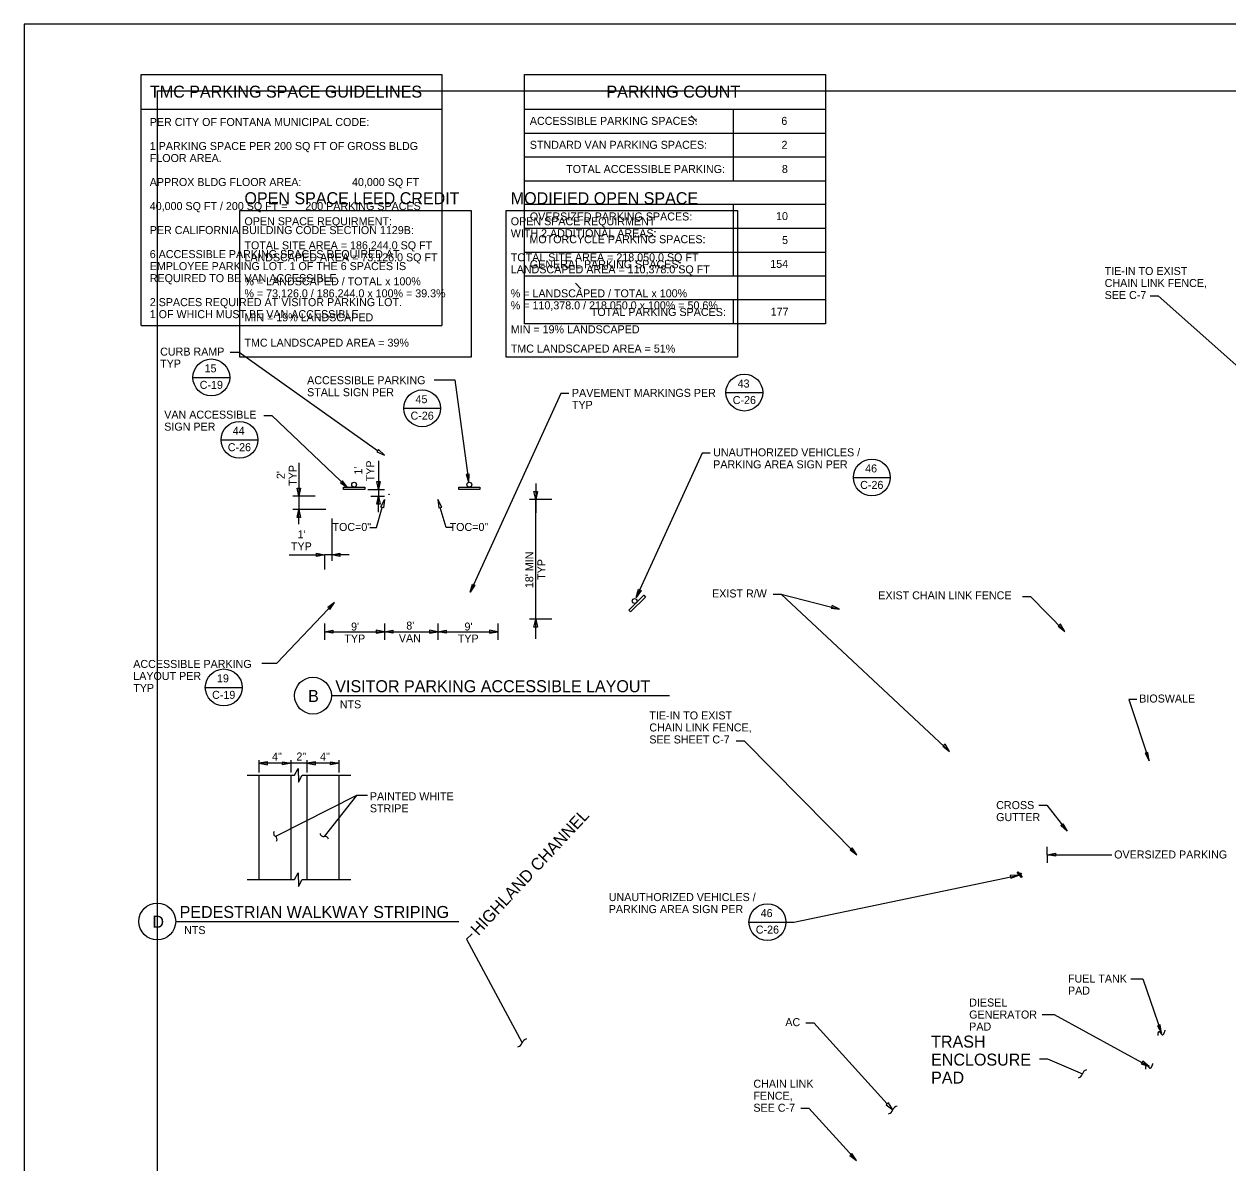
# Model space of a CAD drawing. Extents: x 0 to 4.19, y 0 to 2.5.
# Drawn here: x 0 to 1.504, y 1.078 to 2.5 of the extents above; entities that cross this region are included whole.
import ezdxf

# ---------------------------------------------------------------- set-up
doc = ezdxf.new("R2010")
doc.units = 0
for name, color, linetype in [('C-MARK', 7, 'Continuous'), ('C-PRKG-STRP', 7, 'Continuous'), ('C-RAMP-Bumps', 7, 'Continuous'), ('C-TEXT', 7, 'Continuous'), ('C-TEXT-SUBT', 7, 'Continuous'), ('C-TEXT-TITL', 7, 'Continuous'), ('G-TTLB-OTLN', 7, 'Continuous'), ('G-TTLB-VIEW', 7, 'Continuous'), ('LEED TABLE', 7, 'Continuous'), ('Level 11', 7, 'Continuous'), ('PARING COUNT', 7, 'Continuous')]:
    doc.layers.add(name, color=color, linetype=linetype)

msp = doc.modelspace()

# ---------------------------------------------------------------- linework, layer by layer
at = {"layer": 'C-MARK'}
for p, q in [((0.2109, 2.0587), (0.2569, 2.0587)), ((0.8768, 2.0397), (0.9228, 2.0397)), ((0.4744, 2.0201), (0.5204, 2.0201)), ((0.2461, 1.9808), (0.2921, 1.9808)), ((0.3433, 1.9521), (0.3433, 1.9102)), ((0.4429, 1.9543), (0.4429, 1.9186)), ((0.6391, 1.9261), (0.6391, 1.9061)), ((1.0361, 1.9337), (1.0821, 1.9337)), ((0.3636, 1.9102), (0.3358, 1.9102)), ((0.3433, 1.9102), (0.3433, 1.8936)), ((0.4293, 1.9186), (0.4504, 1.9186)), ((0.433, 1.9102), (0.4504, 1.9102)), ((0.4429, 1.9186), (0.4429, 1.9102)), ((0.4429, 1.8902), (0.4429, 1.9102)), ((0.6595, 1.9061), (0.6316, 1.9061)), ((0.6391, 1.9061), (0.6391, 1.8894)), ((0.6391, 1.7322), (0.6391, 1.9061)), ((0.377, 1.8936), (0.3358, 1.8936)), ((0.3433, 1.8754), (0.3433, 1.8936)), ((0.3845, 1.8823), (0.3845, 1.8297)), ((0.3313, 1.8372), (0.3753, 1.8372)), ((0.3845, 1.8372), (0.3753, 1.8372)), ((0.3753, 1.8362), (0.3753, 1.8188)), ((0.4062, 1.8372), (0.3845, 1.8372)), ((0.9458, 1.7879), (1.0188, 1.7691)), ((0.3753, 1.7512), (0.3753, 1.7309)), ((0.4503, 1.7513), (0.4503, 1.7311)), ((0.4503, 1.7512), (0.4503, 1.7309)), ((0.4503, 1.7512), (0.4503, 1.7309)), ((0.517, 1.7513), (0.517, 1.7311)), ((0.517, 1.7512), (0.517, 1.7309)), ((0.517, 1.7512), (0.517, 1.7309)), ((0.592, 1.7512), (0.592, 1.7309)), ((0.6595, 1.7569), (0.6316, 1.7569)), ((0.3753, 1.741), (0.4503, 1.741)), ((0.4503, 1.741), (0.517, 1.741)), ((0.517, 1.741), (0.592, 1.741)), ((0.2264, 1.6715), (0.2724, 1.6715)), ((0.2935, 1.5652), (0.2935, 1.5808)), ((0.3335, 1.5652), (0.3335, 1.5808)), ((0.3535, 1.5652), (0.3535, 1.5808)), ((0.3935, 1.5652), (0.3935, 1.5808)), ((0.3379, 1.562), (0.3425, 1.5703)), ((0.3425, 1.5703), (0.343, 1.5533)), ((0.2786, 1.562), (0.3379, 1.562)), ((0.343, 1.5533), (0.3475, 1.562)), ((0.3475, 1.562), (0.4084, 1.562)), ((1.278, 1.4625), (1.278, 1.4725)), ((1.278, 1.4625), (1.278, 1.4525)), ((1.278, 1.4625), (1.3589, 1.4625)), ((0.2786, 1.4317), (0.3379, 1.4317)), ((0.3379, 1.4317), (0.3425, 1.4399)), ((0.3425, 1.4399), (0.343, 1.423)), ((0.343, 1.423), (0.3475, 1.4317)), ((0.3475, 1.4317), (0.4084, 1.4317)), ((0.9056, 1.3783), (0.9516, 1.3783))]:
    msp.add_line(p, q, dxfattribs=at)
for points in [[(1.4069, 2.1604), (1.4169, 2.1604), (1.5626, 2.0313)], [(0.5125, 2.0556), (0.5383, 2.0556), (0.5555, 1.9272)], [(0.6805, 2.0384), (0.6705, 2.0384), (0.5573, 1.7903)], [(0.2994, 2.0112), (0.3094, 2.0112), (0.404, 1.921)], [(0.857, 1.9641), (0.847, 1.9641), (0.7648, 1.7838)], [(0.4321, 1.8712), (0.4401, 1.8712), (0.4474, 1.8961)], [(0.5352, 1.8712), (0.5272, 1.8712), (0.5199, 1.8961)], [(0.2972, 1.7018), (0.3158, 1.7017), (0.388, 1.7775)], [(0.9358, 1.7879), (0.9458, 1.7879), (1.1562, 1.5915)], [(1.2471, 1.7852), (1.2571, 1.7852), (1.3003, 1.7414)], [(1.39, 1.6562), (1.38, 1.6562), (1.4054, 1.5799)], [(0.8895, 1.6049), (0.8995, 1.6049), (1.0403, 1.4622)], [(0.3335, 1.5767), (0.2935, 1.5767)], [(0.3535, 1.5767), (0.3335, 1.5767)], [(0.3935, 1.5767), (0.3535, 1.5767)], [(0.4291, 1.5363), (0.4152, 1.5363), (0.3139, 1.4854)], [(0.4152, 1.5363), (0.375, 1.4854)], [(1.2675, 1.5246), (1.2775, 1.5246), (1.303, 1.492)], [(0.9516, 1.3783), (0.9616, 1.3783), (1.2425, 1.437)], [(0.5596, 1.3639), (0.5527, 1.3571), (0.6223, 1.2276)], [(1.3825, 1.3077), (1.3974, 1.3077), (1.4209, 1.2396)], [(0.9764, 1.2527), (0.9864, 1.2527), (1.0784, 1.1514)], [(1.272, 1.2629), (1.2869, 1.2629), (1.4056, 1.1978)], [(1.2686, 1.2076), (1.2786, 1.2076), (1.3222, 1.1889)], [(0.9704, 1.1459), (0.9804, 1.1459), (1.0398, 1.0805)]]:
    msp.add_lwpolyline(points, dxfattribs=at)
for points in [[(0.3991, 1.9217), (0.4255, 1.9217), (0.4255, 1.9186), (0.3991, 1.9186)], [(0.543, 1.9217), (0.5694, 1.9217), (0.5694, 1.9186), (0.543, 1.9186)], [(0.7555, 1.768), (0.7741, 1.7866), (0.7764, 1.7844), (0.7577, 1.7657)], [(1.2413, 1.4412), (1.247, 1.4349), (1.2462, 1.4342), (1.2406, 1.4405)]]:
    msp.add_lwpolyline(points, close=True, dxfattribs=at)
for centre, radius in [((0.2339, 2.0587), 0.023), ((0.8998, 2.0397), 0.023), ((0.4974, 2.0201), 0.023), ((0.2691, 1.9808), 0.023), ((1.0591, 1.9337), 0.023), ((0.4123, 1.9247), 0.003), ((0.5562, 1.9247), 0.003), ((0.7627, 1.7794), 0.003), ((0.2494, 1.6715), 0.023), ((1.2449, 1.4387), 0.00096), ((0.9286, 1.3783), 0.023)]:
    msp.add_circle(centre, radius, dxfattribs=at)
for points in [[(1.4167, 1.2366), (1.4166, 1.2449), (1.4231, 1.2344), (1.4255, 1.2435)], [(1.4014, 1.1948), (1.4013, 1.2031), (1.4077, 1.1926), (1.4101, 1.2018)]]:
    msp.add_open_spline(points, degree=2, dxfattribs=at)
at = {"layer": 'C-PRKG-STRP'}
for p, q in [((0.2935, 1.4317), (0.2935, 1.562)), ((0.3335, 1.4317), (0.3335, 1.562)), ((0.3535, 1.4317), (0.3535, 1.562)), ((0.3935, 1.4317), (0.3935, 1.562))]:
    msp.add_line(p, q, dxfattribs=at)
at = {"layer": 'C-RAMP-Bumps'}
msp.add_circle((0.4558, 1.9126), 0.000313, dxfattribs=at)
at = {"layer": 'C-TEXT'}
for p, q in [((0.3839, 1.6612), (0.8064, 1.6612)), ((0.1894, 1.3792), (0.5432, 1.3792))]:
    msp.add_line(p, q, dxfattribs=at)
msp.add_lwpolyline([(0.2576, 2.0901), (0.2689, 2.0901), (0.4417, 1.9673)], dxfattribs=at)
for points in [[(0.4407, 1.9658), (0.4503, 1.9615), (0.4427, 1.9688)], [(0.3952, 1.9269), (0.404, 1.921), (0.3977, 1.9295)], [(0.445, 1.9286), (0.4429, 1.9186), (0.4408, 1.9286)], [(0.5523, 1.9373), (0.5555, 1.9272), (0.5559, 1.9378)], [(0.3454, 1.9202), (0.3433, 1.9102), (0.3412, 1.9202)], [(0.4408, 1.9002), (0.4429, 1.9102), (0.445, 1.9002)], [(0.6412, 1.9161), (0.6391, 1.9061), (0.637, 1.9161)], [(0.4456, 1.8966), (0.4503, 1.9061), (0.4491, 1.8956)], [(0.5217, 1.8966), (0.517, 1.9061), (0.5182, 1.8956)], [(0.3412, 1.8836), (0.3433, 1.8936), (0.3454, 1.8836)], [(0.3653, 1.8393), (0.3753, 1.8372), (0.3653, 1.8351)], [(0.3945, 1.8351), (0.3845, 1.8372), (0.3945, 1.8393)], [(0.5633, 1.799), (0.5573, 1.7903), (0.56, 1.8005)], [(0.7707, 1.7925), (0.7648, 1.7838), (0.7674, 1.794)], [(0.3821, 1.7687), (0.388, 1.7775), (0.3795, 1.7712)], [(1.0083, 1.7703), (1.0188, 1.7691), (1.0093, 1.7739)], [(0.637, 1.7469), (0.6391, 1.7569), (0.6412, 1.7469)], [(1.2919, 1.7478), (1.3003, 1.7414), (1.2947, 1.7503)], [(0.3857, 1.7392), (0.3753, 1.741), (0.3857, 1.7429)], [(0.4399, 1.7392), (0.4503, 1.741), (0.4399, 1.7429)], [(0.4607, 1.7392), (0.4503, 1.741), (0.4607, 1.7429)], [(0.5066, 1.7392), (0.517, 1.741), (0.5066, 1.7429)], [(0.5274, 1.7392), (0.517, 1.741), (0.5274, 1.7429)], [(0.5816, 1.7392), (0.592, 1.741), (0.5816, 1.7429)], [(1.1479, 1.598), (1.1562, 1.5915), (1.1506, 1.6004)], [(1.4004, 1.5892), (1.4054, 1.5799), (1.4039, 1.5903)], [(0.3039, 1.5786), (0.2935, 1.5767), (0.3039, 1.5749)], [(0.3231, 1.5786), (0.3335, 1.5767), (0.323, 1.5749)], [(0.3639, 1.5786), (0.3535, 1.5767), (0.3639, 1.5749)], [(0.3831, 1.5786), (0.3935, 1.5767), (0.383, 1.5749)], [(1.2978, 1.5012), (1.303, 1.492), (1.295, 1.4989)], [(1.0319, 1.4686), (1.0403, 1.4622), (1.0346, 1.4711)], [(1.2884, 1.4606), (1.278, 1.4625), (1.2884, 1.4643)], [(1.2327, 1.4331), (1.2425, 1.437), (1.2319, 1.4367)], [(1.4159, 1.2489), (1.4209, 1.2396), (1.4194, 1.2501)], [(1.3956, 1.2014), (1.4056, 1.1978), (1.3975, 1.2046)], [(1.077, 1.1502), (1.0854, 1.1437), (1.0797, 1.1527)], [(1.0315, 1.087), (1.0398, 1.0805), (1.0342, 1.0894)]]:
    msp.add_lwpolyline(points, close=True, dxfattribs=at)
for centre in [(0.3609, 1.6612), (0.1664, 1.3792)]:
    msp.add_circle(centre, 0.023, dxfattribs=at)
for centre, radius, start, end in [((0.3162, 1.4893), 0.00447, 149.3032, 239.3033), ((0.3741, 1.4898), 0.00447, 191.7318, 281.7319), ((0.3116, 1.4816), 0.00447, 329.3033, 59.3033), ((0.3759, 1.481), 0.00447, 11.7319, 101.7319), ((0.615, 1.2301), 0.0077, 284.652, 340.4848), ((0.6295, 1.2249), 0.0077, 104.2141, 159.7576), ((1.3148, 1.1911), 0.0077, 287.4184, 343.2513), ((1.3295, 1.1866), 0.0077, 106.9806, 162.5241), ((1.0781, 1.1463), 0.0077, 284.652, 340.4848), ((1.0926, 1.1411), 0.0077, 104.2141, 159.7576)]:
    msp.add_arc(centre, radius, start, end, dxfattribs=at)
at = {"layer": 'G-TTLB-OTLN'}
msp.add_lwpolyline([(0, 0), (3.5, 0), (3.5, 2.5), (0, 2.5)], close=True, dxfattribs=at)
msp.add_lwpolyline([(0, 0), (3.5, 0), (3.5, 2.5), (0, 2.5)], close=True, dxfattribs=at)
at = {"layer": 'G-TTLB-VIEW'}
msp.add_lwpolyline([(0.1667, 2.4167), (3.0729, 2.4167), (3.0729, 0.0833), (0.1667, 0.0833)], close=True, dxfattribs=at)
at = {"layer": 'LEED TABLE'}
for points in [[(0.2696, 2.2672), (0.5586, 2.2672), (0.5586, 2.0839), (0.2696, 2.0839)], [(0.2696, 2.2672), (0.5586, 2.2672), (0.5586, 2.0839), (0.2696, 2.0839)], [(0.6023, 2.2672), (0.8913, 2.2672), (0.8913, 2.0839), (0.6023, 2.0839)]]:
    msp.add_lwpolyline(points, close=True, dxfattribs=at)
at = {"layer": 'Level 11'}
for p, q in [((0.8401, 2.3784), (0.8332, 2.3853)), ((0.6957, 2.1695), (0.6888, 2.1764))]:
    msp.add_line(p, q, dxfattribs=at)
at = {"layer": 'PARING COUNT'}
for p, q in [((0.1462, 2.4369), (0.5219, 2.4369)), ((0.1462, 2.1235), (0.1462, 2.4369)), ((0.5219, 2.4369), (0.5219, 2.1235)), ((0.6252, 2.4369), (1.001, 2.4369)), ((0.6252, 2.1256), (0.6252, 2.4369)), ((1.001, 2.4369), (1.001, 2.1256)), ((0.1462, 2.3937), (0.5219, 2.3937)), ((0.6252, 2.3937), (1.001, 2.3937)), ((0.8859, 2.3937), (0.8859, 2.3043)), ((0.6252, 2.3639), (1.001, 2.3639)), ((0.6252, 2.3341), (1.001, 2.3341)), ((0.6252, 2.3043), (1.001, 2.3043)), ((1.001, 2.2745), (0.6252, 2.2745)), ((0.8859, 2.2745), (0.8859, 2.1852)), ((1.001, 2.2447), (0.6252, 2.2447)), ((1.001, 2.2149), (0.6252, 2.2149)), ((1.001, 2.1852), (0.6252, 2.1852)), ((1.001, 2.1554), (0.6252, 2.1554)), ((0.8859, 2.1554), (0.8859, 2.1256)), ((0.1462, 2.1235), (0.5219, 2.1235)), ((1.001, 2.1256), (0.6252, 2.1256))]:
    msp.add_line(p, q, dxfattribs=at)

# ---------------------------------------------------------------- texts
at = {"layer": 'C-TEXT'}
for s, p in [('TIE-IN TO EXIST', (1.3499, 2.1866)), ('CHAIN LINK FENCE,', (1.3499, 2.1716)), ('SEE C-7', (1.3499, 2.1566)), ('CURB RAMP', (0.17, 2.0859)), ('TYP', (0.17, 2.0709)), ('15', (0.2255, 2.065)), ('C-19', (0.2194, 2.0444)), ('ACCESSIBLE PARKING', (0.3536, 2.0502)), ('STALL SIGN PER', (0.3536, 2.0352)), ('43', (0.8914, 2.046)), ('45', (0.489, 2.0265)), ('PAVEMENT MARKINGS PER', (0.6844, 2.0344)), ('C-26', (0.8853, 2.0254)), ('VAN ACCESSIBLE', (0.1751, 2.0072)), ('C-26', (0.4828, 2.0059)), ('TYP', (0.6844, 2.0194)), ('SIGN PER', (0.1751, 1.9922)), ('44', (0.2607, 1.9871)), ('C-26', (0.2545, 1.9665)), ('UNAUTHORIZED VEHICLES /', (0.8609, 1.9601)), ('PARKING AREA SIGN PER', (0.8609, 1.9451)), ('46', (1.0507, 1.94)), ('C-26', (1.0445, 1.9194)), ('TOC=0"', (0.5316, 1.8669)), ('EXIST R/W', (0.8595, 1.7838)), ('EXIST CHAIN LINK FENCE', (1.0671, 1.7815)), ("9'", (0.4085, 1.7425)), ("8'", (0.4775, 1.7437)), ("9'", (0.5502, 1.7425)), ('TYP', (0.4001, 1.7275)), ('VAN', (0.4682, 1.7279)), ('TYP', (0.5418, 1.7275)), ('ACCESSIBLE PARKING', (0.1364, 1.6958)), ('LAYOUT PER', (0.1364, 1.6808)), ('19', (0.241, 1.6778)), ('TYP', (0.1364, 1.6658)), ('C-19', (0.2349, 1.6572)), ('NTS', (0.3944, 1.6454)), ('TIE-IN TO EXIST', (0.7811, 1.6315)), ('CHAIN LINK FENCE,', (0.7811, 1.6165)), ('SEE SHEET C-7', (0.7811, 1.6015)), ('PAINTED WHITE', (0.432, 1.5305)), ('STRIPE', (0.432, 1.5155)), ('UNAUTHORIZED VEHICLES /', (0.7304, 1.4046)), ('PARKING AREA SIGN PER', (0.7304, 1.3896)), ('46', (0.9202, 1.3846)), ('NTS', (0.1999, 1.3634)), ('C-26', (0.9141, 1.364)), ('AC', (0.951, 1.2484)), ('CHAIN LINK', (0.9111, 1.1715)), ('FENCE,', (0.9111, 1.1565)), ('SEE C-7', (0.9111, 1.1415))]:
    msp.add_text(s, height=0.01, dxfattribs=at).set_placement(p)
for s, rotation, p in [("2'", 90, (0.3256, 1.9317)), ('TYP', 90, (0.3406, 1.9233)), ("1'", 90, (0.4224, 1.9373)), ('TYP', 90, (0.4374, 1.9289)), ("1'", 360, (0.3418, 1.8577)), ('TOC=0"', 360, (0.3853, 1.8669)), ('TYP', 360, (0.3334, 1.8427)), ("18' MIN", 90, (0.6362, 1.7955)), ('TYP', 90, (0.6512, 1.8058)), ('BIOSWALE', 360, (1.3931, 1.6526)), ('4"', 359.7093, (0.3098, 1.5802)), ('2"', 359.7093, (0.3402, 1.5802)), ('4"', 359.7093, (0.3698, 1.5802)), ('CROSS', 360, (1.2144, 1.5195)), ('GUTTER', 360, (1.2144, 1.5045)), ('OVERSIZED PARKING', 360, (1.3618, 1.4578)), ('FUEL TANK', 360, (1.3041, 1.3028)), ('PAD', 360, (1.3041, 1.2878)), ('DIESEL', 360, (1.1807, 1.2729)), ('GENERATOR', 360, (1.1807, 1.2579)), ('PAD', 360, (1.1807, 1.2429))]:
    msp.add_text(s, height=0.01, rotation=rotation, dxfattribs=at).set_placement(p)
at = {"layer": 'C-TEXT-SUBT'}
for s, p in [('VISITOR PARKING ACCESSIBLE LAYOUT', (0.3888, 1.6655)), ('B', (0.3548, 1.6533)), ('PEDESTRIAN WALKWAY STRIPING', (0.1943, 1.3835)), ('D', (0.1603, 1.3713))]:
    msp.add_text(s, height=0.015, dxfattribs=at).set_placement(p)
at = {"layer": 'C-TEXT-TITL'}
msp.add_text('HIGHLAND CHANNEL', height=0.015, rotation=47.1049, dxfattribs=at).set_placement((0.5675, 1.3606))
for s, p in [('TRASH', (1.1331, 1.2216)), ('ENCLOSURE', (1.1331, 1.1991)), ('PAD', (1.1331, 1.1766))]:
    msp.add_text(s, height=0.015, dxfattribs=at).set_placement(p)
at = {"layer": 'LEED TABLE'}
for s, height, p in [('OPEN SPACE LEED CREDIT', 0.015, (0.2753, 2.275)), ('MODIFIED OPEN SPACE', 0.015, (0.608, 2.275)), ('OPEN SPACE REQUIRMENT:', 0.01, (0.2753, 2.2487)), ('OPEN SPACE REQUIRMENT', 0.01, (0.608, 2.2487)), ('WITH 2 ADDITIONAL AREAS:', 0.01, (0.608, 2.2337)), ('TOTAL SITE AREA = 186,244.0 SQ FT', 0.01, (0.2753, 2.2187)), ('LANDSCAPED AREA = 73,126.0 SQ FT', 0.01, (0.2753, 2.2037)), ('TOTAL SITE AREA = 218,050.0 SQ FT', 0.01, (0.608, 2.2037)), ('LANDSCAPED AREA = 110,378.0 SQ FT', 0.01, (0.608, 2.1887)), ('% = LANDSCAPED / TOTAL x 100%', 0.01, (0.2753, 2.1737)), ('% = 73,126.0 / 186,244.0 x 100% = 39.3%', 0.01, (0.2753, 2.1587)), ('% = LANDSCAPED / TOTAL x 100%', 0.01, (0.608, 2.1587)), ('% = 110,378.0 / 218,050.0 x 100% = 50.6%', 0.01, (0.608, 2.1437)), ('MIN = 19% LANDSCAPED', 0.01, (0.2753, 2.1287)), ('MIN = 19% LANDSCAPED', 0.01, (0.608, 2.1137)), ('TMC LANDSCAPED AREA = 39%', 0.01, (0.2753, 2.0971)), ('TMC LANDSCAPED AREA = 51%', 0.01, (0.608, 2.0897))]:
    msp.add_text(s, height=height, dxfattribs=at).set_placement(p)
at = {"layer": 'PARING COUNT'}
for s, height, p in [('TMC PARKING SPACE GUIDELINES', 0.015, (0.1573, 2.4081)), ('PARKING COUNT', 0.015, (0.7275, 2.4081)), ('PER CITY OF FONTANA MUNICIPAL CODE:', 0.01, (0.157, 2.3727)), ('ACCESSIBLE PARKING SPACES:', 0.01, (0.6318, 2.3741)), ('6', 0.01, (0.946, 2.3741)), ('1 PARKING SPACE PER 200 SQ FT OF GROSS BLDG', 0.01, (0.157, 2.3427)), ('STNDARD VAN PARKING SPACES:', 0.01, (0.6318, 2.3442)), ('2', 0.01, (0.9462, 2.3442)), ('FLOOR AREA.', 0.01, (0.157, 2.3277)), ('TOTAL ACCESSIBLE PARKING:', 0.01, (0.6772, 2.314)), ('8', 0.01, (0.9467, 2.314)), ('APPROX BLDG FLOOR AREA:                 40,000 SQ FT', 0.01, (0.157, 2.2977)), ('40,000 SQ FT / 200 SQ FT =      200 PARKING SPACES', 0.01, (0.157, 2.2677)), ('OVERSIZED PARKING SPACES:', 0.01, (0.6318, 2.2547)), ('10', 0.01, (0.9394, 2.2552)), ('PER CALIFORNIA BUILDING CODE SECTION 1129B:', 0.01, (0.157, 2.2377)), ('MOTORCYCLE PARKING SPACES:', 0.01, (0.6313, 2.2263)), ('5', 0.01, (0.9469, 2.2253)), ('6 ACCESSIBLE PARKING SPACES REQUIRED AT', 0.01, (0.157, 2.2077)), ('EMPLOYEE PARKING LOT. 1 OF THE 6 SPACES IS', 0.01, (0.157, 2.1927)), ('GENERAL PARKING SPACES:', 0.01, (0.6318, 2.195)), ('154', 0.01, (0.9322, 2.1955)), ('REQUIRED TO BE VAN ACCESSIBLE.', 0.01, (0.157, 2.1777)), ('2 SPACES REQUIRED AT VISITOR PARKING LOT.  ', 0.01, (0.157, 2.1477)), ('1 OF WHICH MUST BE VAN ACCESSIBLE.', 0.01, (0.157, 2.1327)), ('TOTAL PARKING SPACES:', 0.01, (0.708, 2.1354)), ('177', 0.01, (0.9327, 2.1358))]:
    msp.add_text(s, height=height, dxfattribs=at).set_placement(p)

doc.saveas('drawing.dxf')
